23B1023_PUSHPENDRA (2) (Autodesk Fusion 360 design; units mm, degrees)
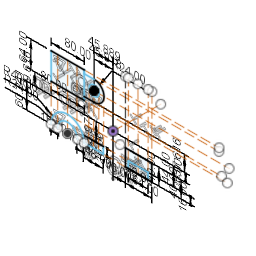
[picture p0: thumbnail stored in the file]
sketch "Sketch1" plane through (0, 0, 0) normal (0, 1, 0) x axis (1, 0, 0)
  line L1 (-149.9151, -29.6164) -> (-69.9151, -29.6164)
  line L2 (-149.9151, -93.6164) -> (-149.9151, -29.6164)
  line L3 (-69.9151, -93.6164) -> (-149.9151, -93.6164)
  line L4 (-69.9151, -29.6164) -> (-69.9151, -93.6164)
  line L5 (-87.3478, -29.6164) -> (-87.3478, -93.6164)
  line L6 (-134.0077, -29.6164) -> (-134.0127, -93.6164)
  line L7 (-69.9151, -37.6164) -> (-69.9151, -29.6164)
  line L8 (-69.9151, -85.6164) -> (-69.9151, -93.6164)
  line L9 (-45.918, -85.6164) -> (-69.9151, -85.6164)
  line L10 (-45.918, -37.6164) -> (-69.9151, -37.6164)
  line L11 (-134.1917, 60.241) -> (-150.1917, 60.241)
  line L12 (-87.5372, 59.4287) -> (-71.5372, 59.4287)
  line L13 (-23.5404, 59.9763) -> (-71.5372, 59.4287)
  line L14 (-23.3578, 43.9774) -> (-23.5404, 59.9763)
  line L15 (-47.5388, 59.7025) -> (-45.918, -61.6164)
  line L16 (-35.2763, 59.8424) -> (-33.8888, -61.7697)
  line L17 (-59.2764, 59.5686) -> (-57.8889, -62.0435)
  line L18 (94, 60) -> (30, 60)
  line L19 (30, 20) -> (30, 60)
  line L20 (94, 20) -> (94, 60)
  line L21 (30, 20) -> (94, 20)
  line L22 (84.8282, 60) -> (36.8282, 60)
  line L23 (36.8282, 44) -> (36.8282, 60)
  line L24 (84.8282, 44) -> (84.8282, 60)
  line L25 (36.8282, 44) -> (84.8282, 44)
  line L26 (-23.3578, 43.9774) -> (-73.4648, 43.9774)
  line L27 (-110.1609, 59.8958) -> (-109.9151, -93.6164)
  line L28 (-110.1405, 19.8958) -> (16.7648, 20)
  line L29 (30, -130) -> (30, 20)
  line L30 (263.1722, -36.7645) -> (-45.918, -37.6164)
  line L31 (94.4134, -130) -> (94, 20)
  line L32 (37.3078, -129.9999) -> (36.8282, 44)
  line L33 (85.3078, -129.9999) -> (84.8282, 44)
  line L34 (281.5252, -62.2906) -> (-45.918, -61.6164)
  line L35 (60.4382, -129.4093) -> (60.8282, 60)
  line L36 (256.7838, -85.6164) -> (-45.918, -85.6164)
  line L37 (257.088, -93.6164) -> (-69.9151, -93.6164)
  line L38 (115.6319, -114.199) -> (0, 0)
  line L39 (277.1661, -29.6867) -> (30, -29.6282)
  arc A1 centre (-45.918, -61.6164) radius 24 clockwise from (-45.918, -37.6164) to (-45.918, -85.6164)
  circle C1 centre (-45.8888, -61.9066) radius 12.0008
  arc A2 centre (-110.1609, 59.8958) radius 40 clockwise from (-70.1609, 59.9252) to (-150.1609, 59.8846)
  arc A3 centre (-110.1917, 60.3877) radius 24 clockwise from (-86.1917, 60.3877) to (-134.1917, 60.3877)
  arc A4 centre (23695.0154, 314.5904) radius 23719.917 clockwise from (-21.918, -61.6164) to (-23.3578, 43.9774)
  arc A5 centre (-21017.5243, -29.6164) radius 20930.1765 clockwise from (-87.5372, 59.4287) to (-87.3478, -29.6164)
  arc A6 centre (-21279.9186, -27.9763) radius 21145.9109 clockwise from (-134.1917, 60.241) to (-134.0077, -29.6164)
  arc A7 centre (-16443.5151, -29.6164) radius 16293.6 clockwise from (-150.1609, 59.8846) to (-149.9151, -29.6164)
  arc A8 centre (30, -60526.9064) radius 60586.9064 clockwise from (-23.5404, 59.9763) to (30, 60)
  arc A9 centre (36.8282, -80042.1441) radius 80086.1441 clockwise from (-23.3578, 43.9774) to (36.8282, 44)
  arc A10 centre (-69.9151, -422348.5167) radius 422318.9003 clockwise from (-69.9151, -29.6164) to (30, -29.6282)
  point P6 (-87.3478, -93.6164)
  point P7 (-87.3478, -29.6164)
  point P8 (-134.0127, -93.6164)
  point P9 (-134.0077, -29.6164)
  point P10 (-69.9151, -37.6164)
  point P11 (-69.9151, -85.6164)
  point P28 (-21.918, -61.6164)
  point P14 (-45.918, -61.6164)
  point P30 (-45.918, -61.6164)
  point P31 (-47.5388, 59.7025)
  point P32 (-33.8888, -61.7697)
  point P33 (-35.2763, 59.8424)
  point P34 (-57.8889, -62.0435)
  point P35 (-59.2764, 59.5686)
  point P40 (36.8282, 60)
  point P41 (84.8282, 60)
  point P44 (-73.4648, 43.9774)
  point P45 (-109.9151, -93.6164)
  point P22 (-110.1609, 59.8958)
  point P46 (-110.1609, 59.8958)
  point P53 (-110.1405, 19.8958)
  point P59 (-45.918, -61.6164)
  point P61 (60.8282, 60)
  point P1 (0, 0)
  point P65 (0, 0)
  point P67 (30, -29.6282)
  point P2 (-69.9151, -29.6164)
  point P3 (-149.9151, -29.6164)
  point P4 (-149.9151, -93.6164)
  point P5 (-69.9151, -93.6164)
  point P16 (-150.1917, 60.241)
  point P17 (-134.1917, 60.241)
  point P18 (-71.5372, 59.4287)
  point P19 (-87.5372, 59.4287)
  point P26 (-23.5404, 59.9763)
  point P27 (-23.3578, 43.9774)
  point P36 (30, 60)
  point P37 (94, 60)
  point P38 (30, 20)
  point P39 (94, 20)
  point P42 (36.8282, 44)
  point P15 (-45.8888, -61.9066)
  horizontal L1
  perpendicular L1 L2
  perpendicular L2 L3
  coincident L3 P6
  perpendicular L3 L5
  coincident L1 P7
  coincident L3 P8
  coincident L1 P9
  coincident L4 P10
  perpendicular L1 L7
  coincident L4 P11
  perpendicular L3 L8
  perpendicular L4 L9
  perpendicular L7 L10
  tangent L9 A1
  tangent L10 A1
  horizontal L11
  horizontal L12
  perpendicular L13 L14
  midpoint A1 P28
  tangent L14 A4
  coincident P14 P30
  midpoint L13 P31
  coincident C1 P32
  tangent C1 L16
  coincident L13 P33
  perpendicular L13 L16
  coincident C1 P34
  tangent C1 L17
  coincident L13 P35
  perpendicular L13 L17
  horizontal L18
  perpendicular L18 L19
  perpendicular L18 L20
  coincident L18 P40
  coincident L18 P41
  perpendicular L18 L23
  perpendicular L18 L24
  coincident A2 P44
  horizontal L26
  midpoint L3 P45
  coincident P22 P46
  tangent L5 A5
  tangent L6 A6
  tangent L2 A7
  tangent L18 A8
  tangent L25 A9
  midpoint A2 P53
  perpendicular L21 L29
  perpendicular L30 L31
  perpendicular L30 L32
  perpendicular L30 L33
  coincident P14 P59
  midpoint L22 P61
  perpendicular L34 L35
  coincident P1 P65
  coincident L38 P67
  coincident L29 P67
  tangent L1 A10
  dimension "d1" distance P2 P3 = 80
  dimension "d2" distance P3 P4 = 64
  dimension "d3" distance P4 P5 = 80
  dimension "d11" radius A1 = 24
  dimension "d13" distance P16 P17 = 16
  dimension "d14" distance P18 P19 = 16
  dimension "d15" radius A2 = 40
  dimension "d16" radius A3 = 24
  dimension "d17" distance P18 P26 = 48
  dimension "d18" distance P26 P27 = 16
  dimension "d21" distance P36 P37 = 64
  dimension "d22" distance P36 P38 = 40
  dimension "d23" distance P37 P39 = 40
  dimension "d25" distance P40 P41 = 48
  dimension "d26" distance P40 P42 = 16
  dimension "d28" distance P1 L21 = 20
  dimension "d29" distance P1 L19 = 30
  dimension "d30" distance P1 L1 = 29.6164
  dimension "d32" distance P1 L26 = 43.9774
  dimension "d37" distance P1 L11 = 60.241
  dimension "d38" distance P1 L10 = 37.6164
  dimension "d39" distance P1 P14 = 45.918
  dimension "d40" distance P1 P15 = 45.8888
  dimension "d42" distance P1 L25 = 44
